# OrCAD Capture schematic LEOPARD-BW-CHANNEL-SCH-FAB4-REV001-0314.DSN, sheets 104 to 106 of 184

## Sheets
104 067_DDR4 DIMM CPU1 CHH-2: size A3; title: DDR4 DIMM CPU1 CHH-2
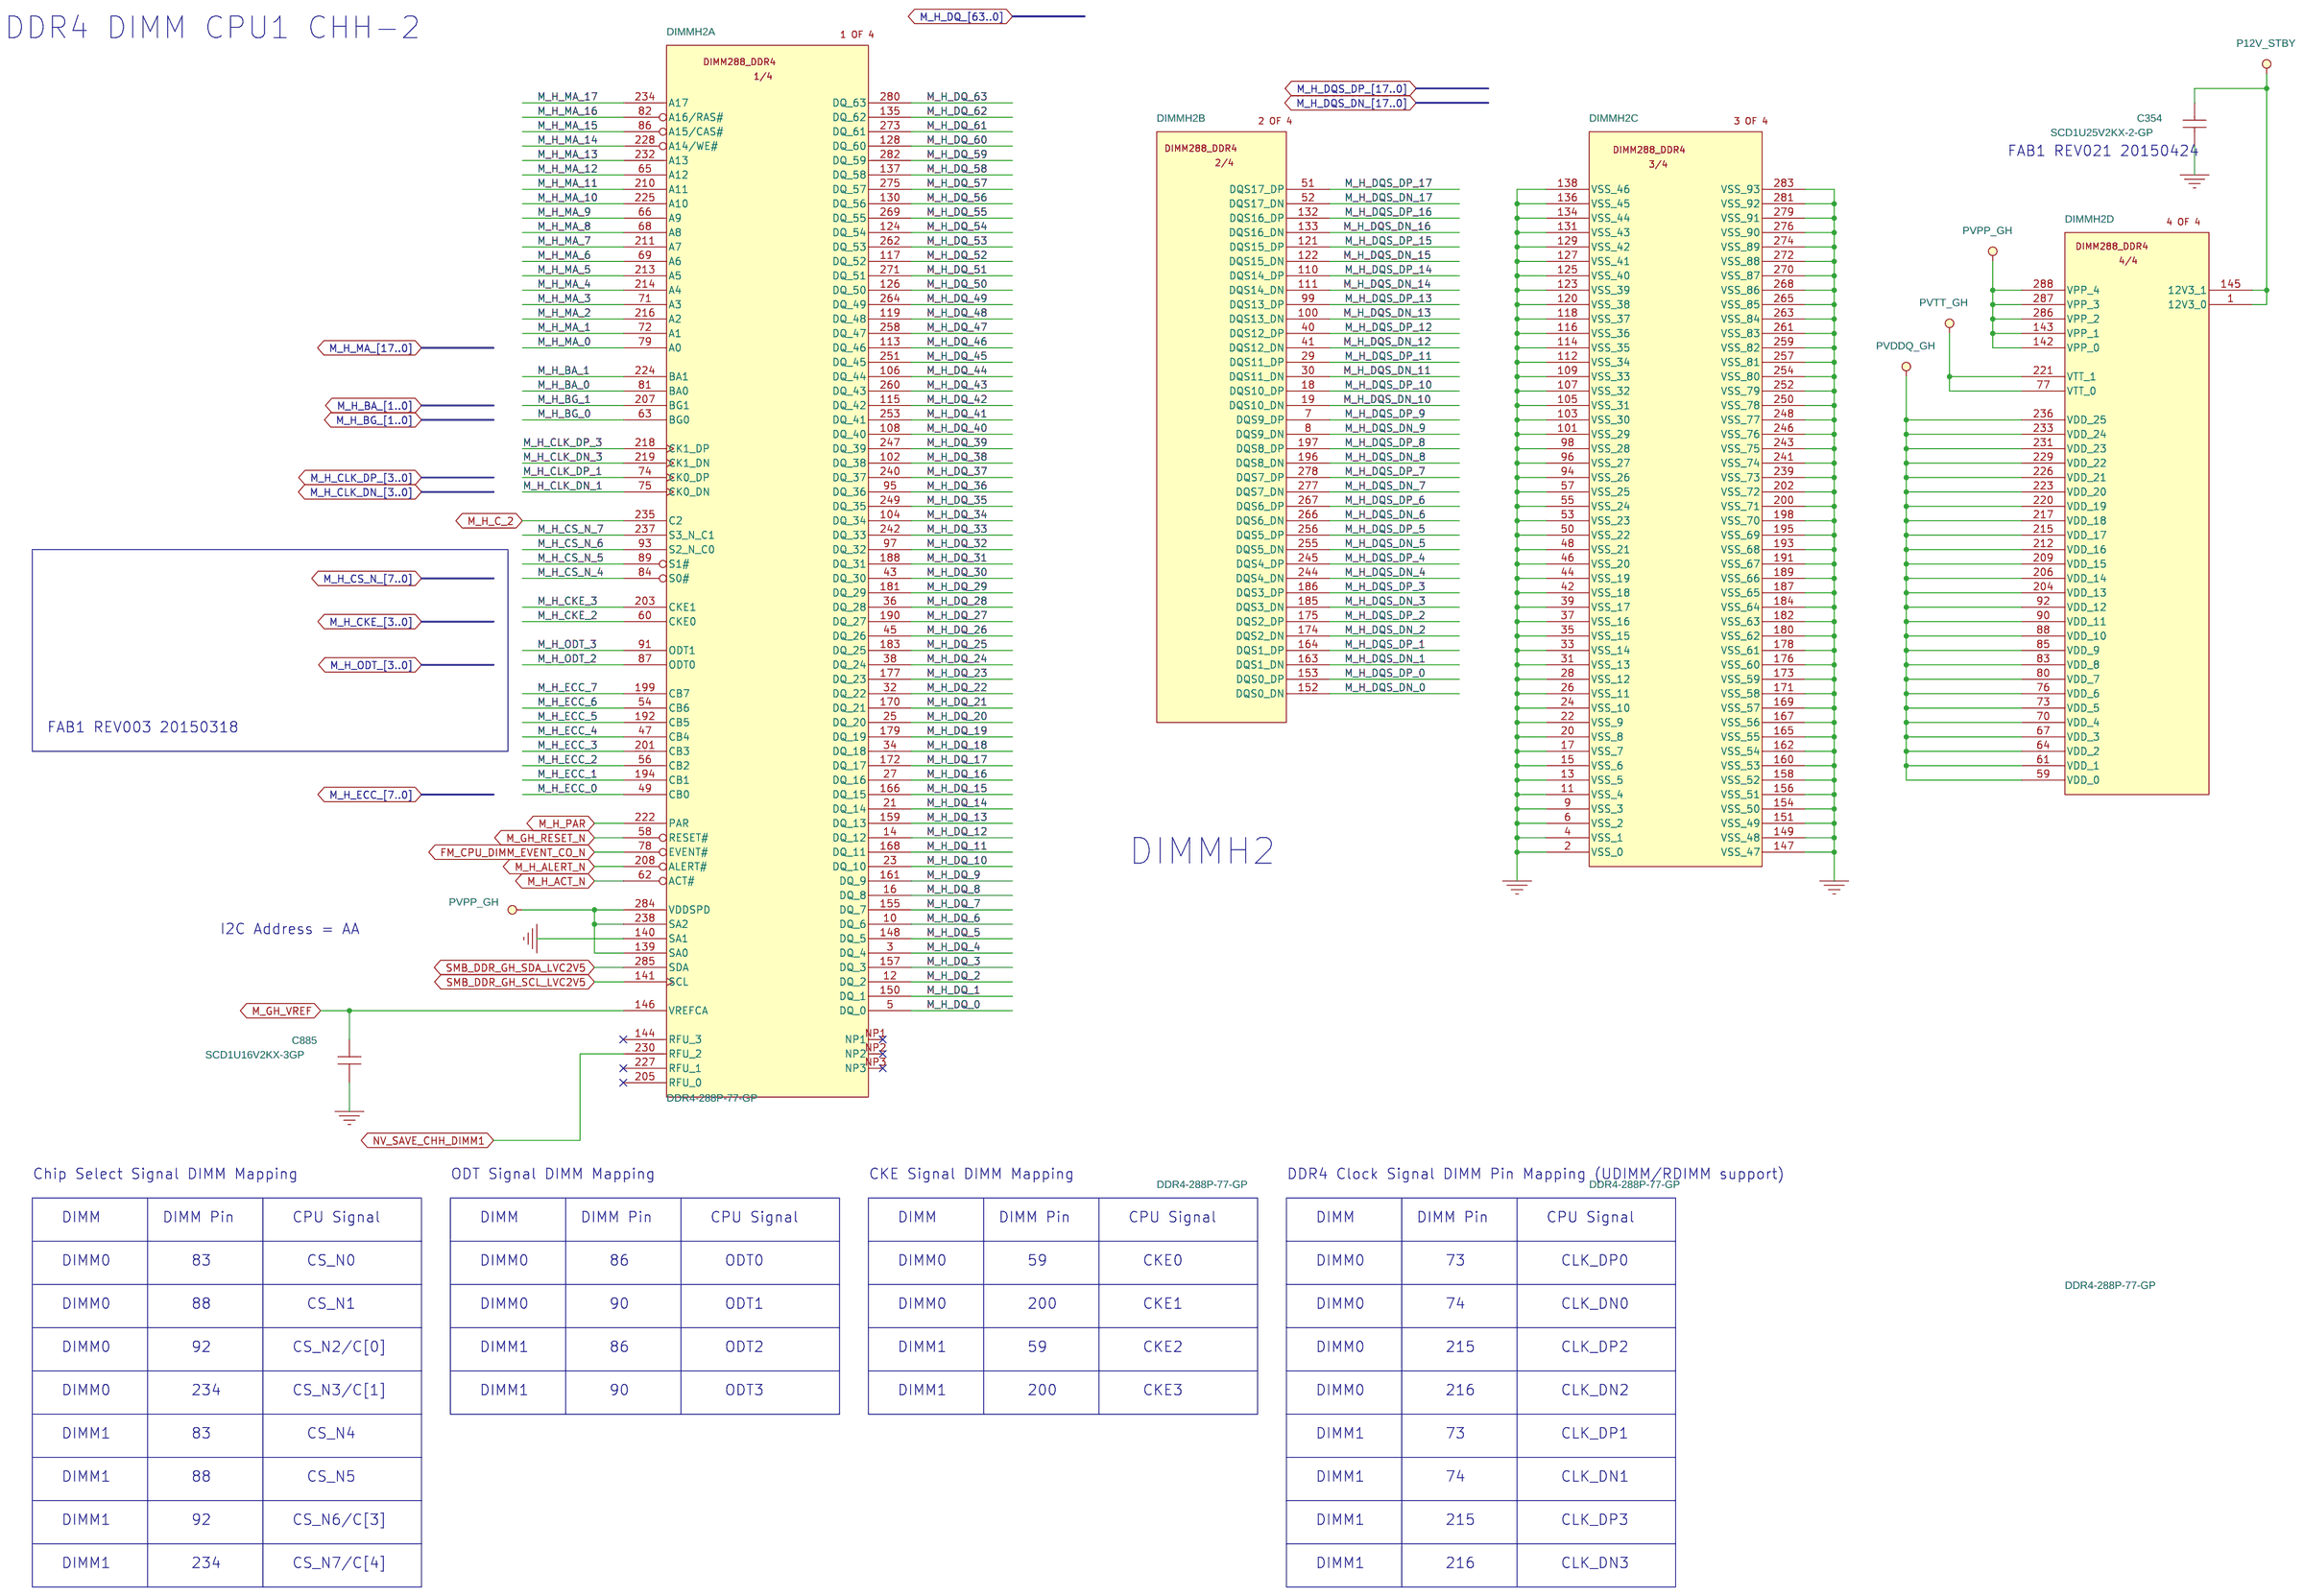
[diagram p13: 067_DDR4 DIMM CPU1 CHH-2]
105 066_DDR4 DIMM CPU1 CHH-1: size A3; title: DDR4 DIMM CPU1 CHH-1
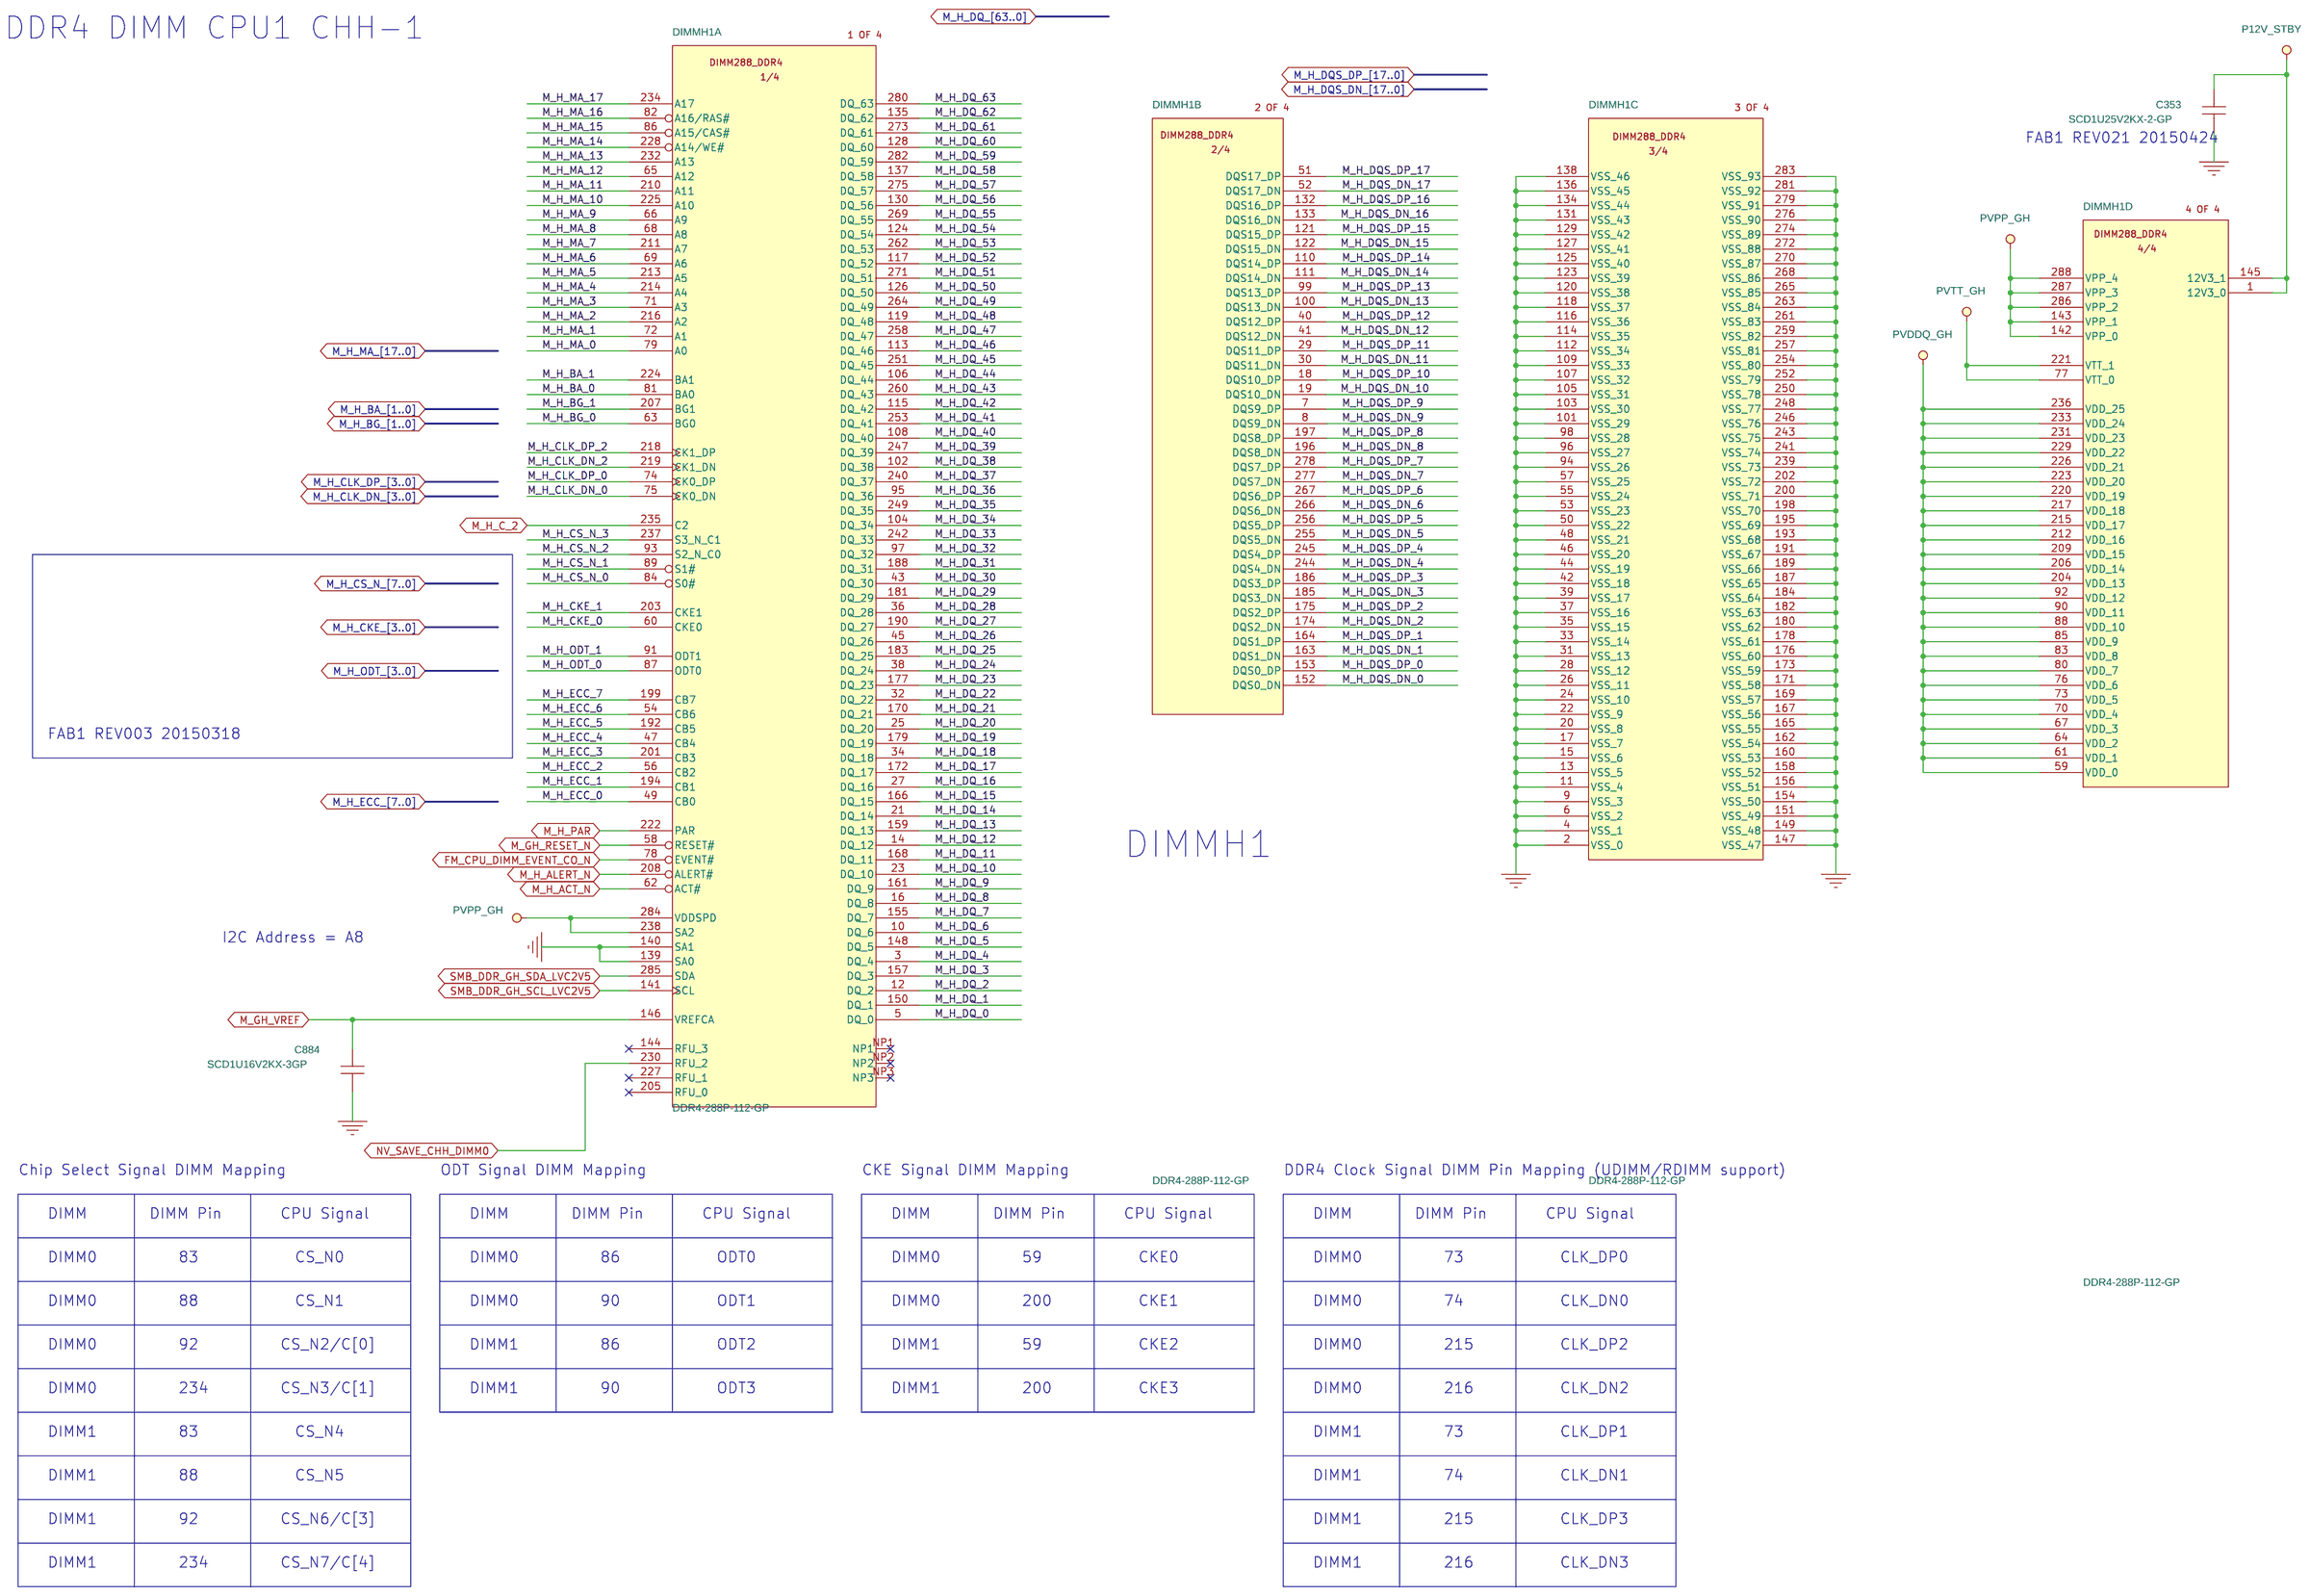
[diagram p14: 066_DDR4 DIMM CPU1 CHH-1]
106 065_DDR4 DIMM CPU1 CHG-2: size A3; title: DDR4 DIMM CPU1 CHG-2
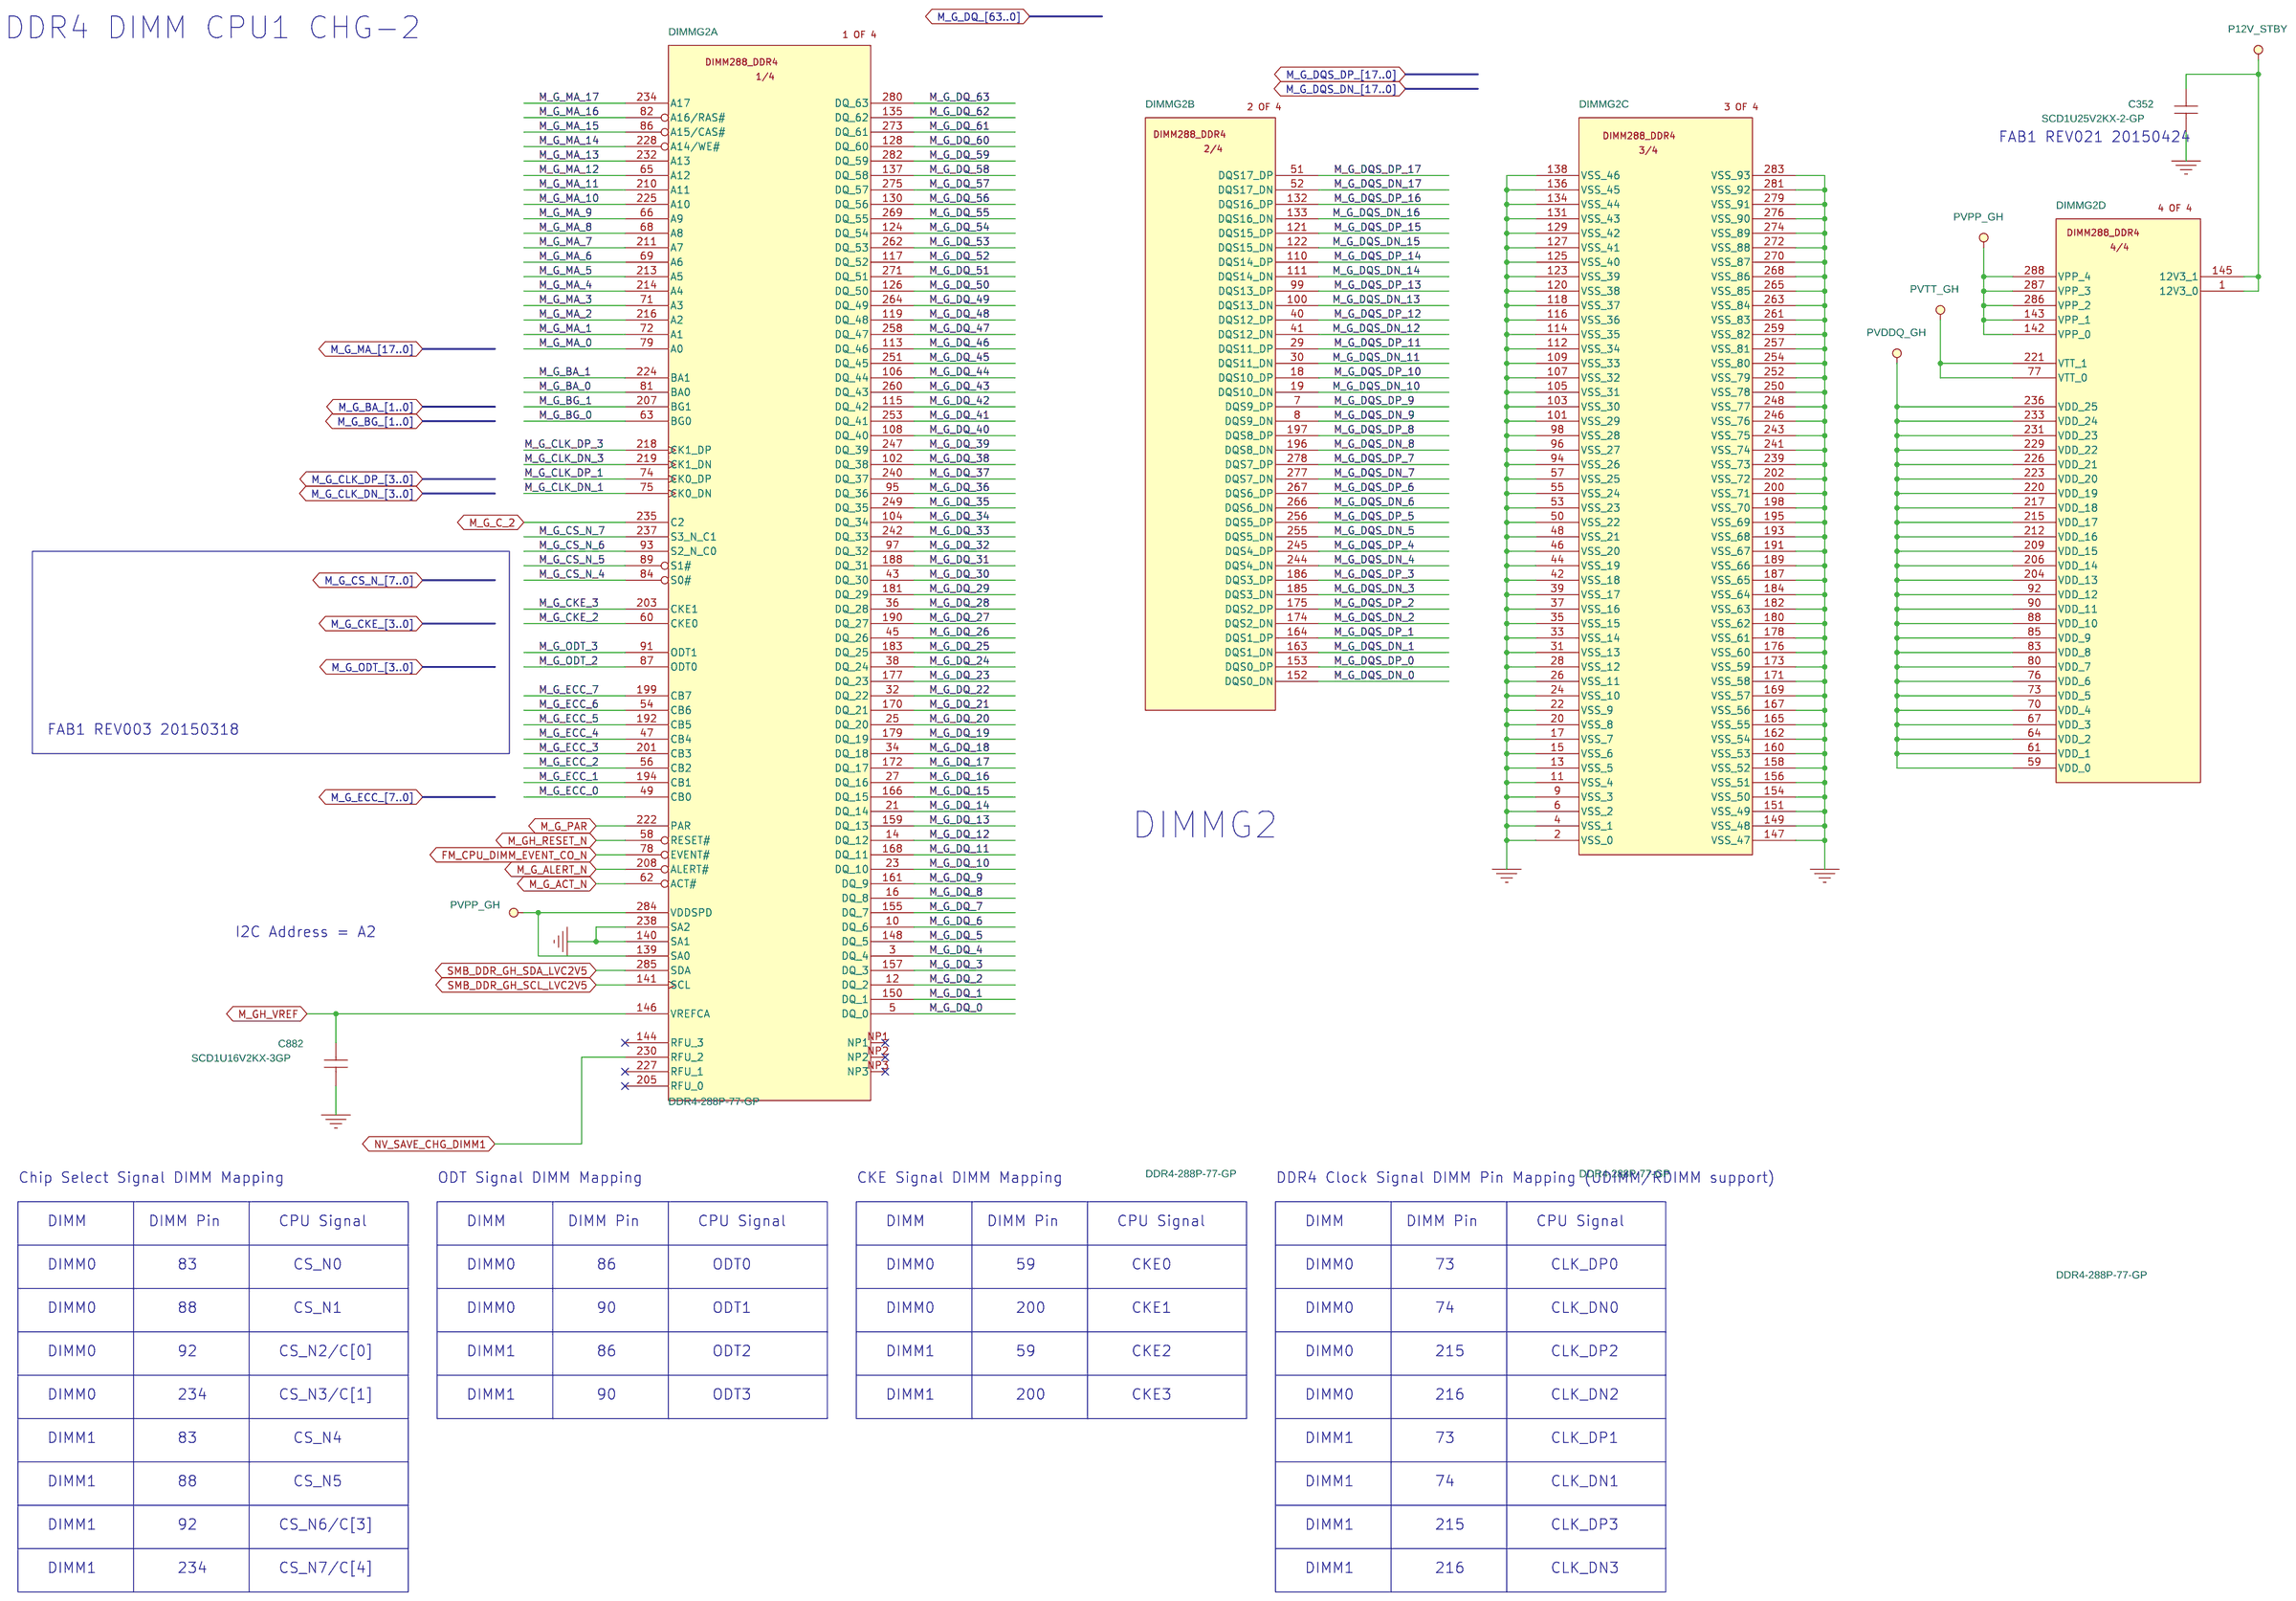
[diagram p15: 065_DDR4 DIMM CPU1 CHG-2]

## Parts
sheet 065_DDR4 DIMM CPU1 CHG-2
C352  SCD1U25V2KX-2-GP  [C402H22]
C882  SCD1U16V2KX-3GP  [C402H22]
DIMMG2  DDR4-288P-77-GP  [10124632-0001113LF]  (sections A,B,C,D)
sheet 066_DDR4 DIMM CPU1 CHH-1
C353  SCD1U25V2KX-2-GP  [C402H22]
C884  SCD1U16V2KX-3GP  [C402H22]
DIMMH1  DDR4-288P-112-GP  [10124632-0001113LF]  (sections A,B,C,D)
sheet 067_DDR4 DIMM CPU1 CHH-2
C354  SCD1U25V2KX-2-GP  [C402H22]
C885  SCD1U16V2KX-3GP  [C402H22]
DIMMH2  DDR4-288P-77-GP  [10124632-0001113LF]  (sections A,B,C,D)

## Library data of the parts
C352-C354 = SCD1U25V2KX-2-GP: CHIP CAP C 0.1U 25V K0402 X7R; GREENDFACTOR: R2_SA;HF_SA;G_SA;; Part Number: 78.10422.2FL; Part Type: SMD-BCG4; SPEC: http://wpqssvr.wistron.com.tw:7001/wpqs/servlet/COM.qpart.Attachment?PartNumber=78.10422.2FL
C882 C884 C885 = SCD1U16V2KX-3GP: CHIP CAP C 0.1U 16V K0402 X7R; CATEGORIES: CAP_1.xV; GREENDFACTOR: R2_SA;HF_SA;G_SA;; MAIN_SOURCE: M; Part Number: 78.10421.2FL; Part Type: SMD-BCG; SPEC: http://wpqssvr.wistron.com.tw:7001/wpqs/servlet/COM.qpart.Attachment?PartNumber=78.10421.2FL
DIMMG2 DIMMH2 = DDR4-288P-77-GP: SKT DIMM DDR4 288P 10124632-0001001LF; GREENDFACTOR: R2_SA;; POP?: 022.10010.0B11; Part Number: 22.10244.1A1; Part Type: SOCKET-G1; SPEC: http://wpqssvr.wistron.com.tw:7001/wpqs/servlet/COM.qpart.Attachment?PartNumber=22.10244.1A1
DIMMH1 = DDR4-288P-112-GP: SKT DIMM DDR4 288P 10124632-0003001LF; GREENDFACTOR: R2_C;; POP?: 022.10010.0E11; Part Number: 022.10010.0B91; Part Type: SOCKET-G2; SPEC: http://wpqssvr.wistron.com.tw:7001/wpqs/servlet/COM.qpart.Attachment?PartNumber=022.10010.0B91

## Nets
GND: C352.2 C353.2 C354.2 C882.2 C884.2 C885.2 DIMMG2.2(VSS_0) DIMMG2.4(VSS_1) DIMMG2.6(VSS_2) DIMMG2.9(VSS_3) DIMMG2.11(VSS_4) DIMMG2.13(VSS_5) DIMMG2.15(VSS_6) DIMMG2.17(VSS_7) DIMMG2.20(VSS_8) DIMMG2.22(VSS_9) DIMMG2.24(VSS_10) DIMMG2.26(VSS_11) DIMMG2.28(VSS_12) DIMMG2.31(VSS_13) DIMMG2.33(VSS_14) DIMMG2.35(VSS_15) DIMMG2.37(VSS_16) DIMMG2.39(VSS_17) DIMMG2.42(VSS_18) DIMMG2.44(VSS_19) DIMMG2.46(VSS_20) DIMMG2.48(VSS_21) DIMMG2.50(VSS_22) DIMMG2.53(VSS_23) DIMMG2.55(VSS_24) DIMMG2.57(VSS_25) DIMMG2.94(VSS_26) DIMMG2.96(VSS_27) DIMMG2.98(VSS_28) DIMMG2.101(VSS_29) DIMMG2.103(VSS_30) DIMMG2.105(VSS_31) DIMMG2.107(VSS_32) DIMMG2.109(VSS_33) DIMMG2.112(VSS_34) DIMMG2.114(VSS_35) DIMMG2.116(VSS_36) DIMMG2.118(VSS_37) DIMMG2.120(VSS_38) DIMMG2.123(VSS_39) DIMMG2.125(VSS_40) DIMMG2.127(VSS_41) DIMMG2.129(VSS_42) DIMMG2.131(VSS_43) DIMMG2.134(VSS_44) DIMMG2.136(VSS_45) DIMMG2.138(VSS_46) DIMMG2.140(SA1) DIMMG2.147(VSS_47) DIMMG2.149(VSS_48) DIMMG2.151(VSS_49) DIMMG2.154(VSS_50) DIMMG2.156(VSS_51) DIMMG2.158(VSS_52) DIMMG2.160(VSS_53) DIMMG2.162(VSS_54) DIMMG2.165(VSS_55) DIMMG2.167(VSS_56) DIMMG2.169(VSS_57) DIMMG2.171(VSS_58) DIMMG2.173(VSS_59) DIMMG2.176(VSS_60) DIMMG2.178(VSS_61) DIMMG2.180(VSS_62) DIMMG2.182(VSS_63) DIMMG2.184(VSS_64) DIMMG2.187(VSS_65) DIMMG2.189(VSS_66) DIMMG2.191(VSS_67) DIMMG2.193(VSS_68) DIMMG2.195(VSS_69) DIMMG2.198(VSS_70) DIMMG2.200(VSS_71) DIMMG2.202(VSS_72) DIMMG2.238(SA2) DIMMG2.239(VSS_73) DIMMG2.241(VSS_74) DIMMG2.243(VSS_75) DIMMG2.246(VSS_76) DIMMG2.248(VSS_77) DIMMG2.250(VSS_78) DIMMG2.252(VSS_79) DIMMG2.254(VSS_80) DIMMG2.257(VSS_81) DIMMG2.259(VSS_82) DIMMG2.261(VSS_83) DIMMG2.263(VSS_84) DIMMG2.265(VSS_85) DIMMG2.268(VSS_86) DIMMG2.270(VSS_87) DIMMG2.272(VSS_88) DIMMG2.274(VSS_89) DIMMG2.276(VSS_90) DIMMG2.279(VSS_91) DIMMG2.281(VSS_92) DIMMG2.283(VSS_93) DIMMH1.2(VSS_0) DIMMH1.4(VSS_1) DIMMH1.6(VSS_2) DIMMH1.9(VSS_3) DIMMH1.11(VSS_4) DIMMH1.13(VSS_5) DIMMH1.15(VSS_6) DIMMH1.17(VSS_7) DIMMH1.20(VSS_8) DIMMH1.22(VSS_9) DIMMH1.24(VSS_10) DIMMH1.26(VSS_11) DIMMH1.28(VSS_12) DIMMH1.31(VSS_13) DIMMH1.33(VSS_14) DIMMH1.35(VSS_15) DIMMH1.37(VSS_16) DIMMH1.39(VSS_17) DIMMH1.42(VSS_18) DIMMH1.44(VSS_19) DIMMH1.46(VSS_20) DIMMH1.48(VSS_21) DIMMH1.50(VSS_22) DIMMH1.53(VSS_23) DIMMH1.55(VSS_24) DIMMH1.57(VSS_25) DIMMH1.94(VSS_26) DIMMH1.96(VSS_27) DIMMH1.98(VSS_28) DIMMH1.101(VSS_29) DIMMH1.103(VSS_30) DIMMH1.105(VSS_31) DIMMH1.107(VSS_32) DIMMH1.109(VSS_33) DIMMH1.112(VSS_34) DIMMH1.114(VSS_35) DIMMH1.116(VSS_36) DIMMH1.118(VSS_37) DIMMH1.120(VSS_38) DIMMH1.123(VSS_39) DIMMH1.125(VSS_40) DIMMH1.127(VSS_41) DIMMH1.129(VSS_42) DIMMH1.131(VSS_43) DIMMH1.134(VSS_44) DIMMH1.136(VSS_45) DIMMH1.138(VSS_46) DIMMH1.139(SA0) DIMMH1.140(SA1) DIMMH1.147(VSS_47) DIMMH1.149(VSS_48) DIMMH1.151(VSS_49) DIMMH1.154(VSS_50) DIMMH1.156(VSS_51) DIMMH1.158(VSS_52) DIMMH1.160(VSS_53) DIMMH1.162(VSS_54) DIMMH1.165(VSS_55) DIMMH1.167(VSS_56) DIMMH1.169(VSS_57) DIMMH1.171(VSS_58) DIMMH1.173(VSS_59) DIMMH1.176(VSS_60) DIMMH1.178(VSS_61) DIMMH1.180(VSS_62) DIMMH1.182(VSS_63) DIMMH1.184(VSS_64) DIMMH1.187(VSS_65) DIMMH1.189(VSS_66) DIMMH1.191(VSS_67) DIMMH1.193(VSS_68) DIMMH1.195(VSS_69) DIMMH1.198(VSS_70) DIMMH1.200(VSS_71) DIMMH1.202(VSS_72) DIMMH1.239(VSS_73) DIMMH1.241(VSS_74) DIMMH1.243(VSS_75) DIMMH1.246(VSS_76) DIMMH1.248(VSS_77) DIMMH1.250(VSS_78) DIMMH1.252(VSS_79) DIMMH1.254(VSS_80) DIMMH1.257(VSS_81) DIMMH1.259(VSS_82) DIMMH1.261(VSS_83) DIMMH1.263(VSS_84) DIMMH1.265(VSS_85) DIMMH1.268(VSS_86) DIMMH1.270(VSS_87) DIMMH1.272(VSS_88) DIMMH1.274(VSS_89) DIMMH1.276(VSS_90) DIMMH1.279(VSS_91) DIMMH1.281(VSS_92) DIMMH1.283(VSS_93) DIMMH2.2(VSS_0) DIMMH2.4(VSS_1) DIMMH2.6(VSS_2) DIMMH2.9(VSS_3) DIMMH2.11(VSS_4) DIMMH2.13(VSS_5) DIMMH2.15(VSS_6) DIMMH2.17(VSS_7) DIMMH2.20(VSS_8) DIMMH2.22(VSS_9) DIMMH2.24(VSS_10) DIMMH2.26(VSS_11) DIMMH2.28(VSS_12) DIMMH2.31(VSS_13) DIMMH2.33(VSS_14) DIMMH2.35(VSS_15) DIMMH2.37(VSS_16) DIMMH2.39(VSS_17) DIMMH2.42(VSS_18) DIMMH2.44(VSS_19) DIMMH2.46(VSS_20) DIMMH2.48(VSS_21) DIMMH2.50(VSS_22) DIMMH2.53(VSS_23) DIMMH2.55(VSS_24) DIMMH2.57(VSS_25) DIMMH2.94(VSS_26) DIMMH2.96(VSS_27) DIMMH2.98(VSS_28) DIMMH2.101(VSS_29) DIMMH2.103(VSS_30) DIMMH2.105(VSS_31) DIMMH2.107(VSS_32) DIMMH2.109(VSS_33) DIMMH2.112(VSS_34) DIMMH2.114(VSS_35) DIMMH2.116(VSS_36) DIMMH2.118(VSS_37) DIMMH2.120(VSS_38) DIMMH2.123(VSS_39) DIMMH2.125(VSS_40) DIMMH2.127(VSS_41) DIMMH2.129(VSS_42) DIMMH2.131(VSS_43) DIMMH2.134(VSS_44) DIMMH2.136(VSS_45) DIMMH2.138(VSS_46) DIMMH2.140(SA1) DIMMH2.147(VSS_47) DIMMH2.149(VSS_48) DIMMH2.151(VSS_49) DIMMH2.154(VSS_50) DIMMH2.156(VSS_51) DIMMH2.158(VSS_52) DIMMH2.160(VSS_53) DIMMH2.162(VSS_54) DIMMH2.165(VSS_55) DIMMH2.167(VSS_56) DIMMH2.169(VSS_57) DIMMH2.171(VSS_58) DIMMH2.173(VSS_59) DIMMH2.176(VSS_60) DIMMH2.178(VSS_61) DIMMH2.180(VSS_62) DIMMH2.182(VSS_63) DIMMH2.184(VSS_64) DIMMH2.187(VSS_65) DIMMH2.189(VSS_66) DIMMH2.191(VSS_67) DIMMH2.193(VSS_68) DIMMH2.195(VSS_69) DIMMH2.198(VSS_70) DIMMH2.200(VSS_71) DIMMH2.202(VSS_72) DIMMH2.239(VSS_73) DIMMH2.241(VSS_74) DIMMH2.243(VSS_75) DIMMH2.246(VSS_76) DIMMH2.248(VSS_77) DIMMH2.250(VSS_78) DIMMH2.252(VSS_79) DIMMH2.254(VSS_80) DIMMH2.257(VSS_81) DIMMH2.259(VSS_82) DIMMH2.261(VSS_83) DIMMH2.263(VSS_84) DIMMH2.265(VSS_85) DIMMH2.268(VSS_86) DIMMH2.270(VSS_87) DIMMH2.272(VSS_88) DIMMH2.274(VSS_89) DIMMH2.276(VSS_90) DIMMH2.279(VSS_91) DIMMH2.281(VSS_92) DIMMH2.283(VSS_93) ; also on sheet 1 2 3 4 5 6 7 8 9 10 11 12 13 14 15 16 17 18 19 20 21 22 23 24 25 26 27 28 29 30 31 32 33 34 35 36 37 38 39 44 46 47 49 50 51 52 53 54 55 56 57 58 59 60 61 62 63 64 65 66 69 70 71 73 74 75 76 78 79 80 81 82 83 84 86 87 88 89 90 91 92 93 94 95 96 97 98 99 100 101 102 103 107 108 109 110 111 112 113 114 115 116 117 118 119 128 129 138 139 159 160 161 166 168 169 170 171 172 173 174 175 176 177 180 181 182 183 184
P12V_STBY: C352.1 C353.1 C354.1 DIMMG2.1(12V3_0) DIMMG2.145(12V3_1) DIMMH1.1(12V3_0) DIMMH1.145(12V3_1) DIMMH2.1(12V3_0) DIMMH2.145(12V3_1) ; also on sheet 2 3 4 7 9 10 11 12 13 17 18 22 23 27 28 32 36 59 60 75 95 107 108 109 110 111 112 113 114 115 116 117 118 119
PVDDQ_GH: DIMMG2.59(VDD_0) DIMMG2.61(VDD_1) DIMMG2.64(VDD_2) DIMMG2.67(VDD_3) DIMMG2.70(VDD_4) DIMMG2.73(VDD_5) DIMMG2.76(VDD_6) DIMMG2.80(VDD_7) DIMMG2.83(VDD_8) DIMMG2.85(VDD_9) DIMMG2.88(VDD_10) DIMMG2.90(VDD_11) DIMMG2.92(VDD_12) DIMMG2.204(VDD_13) DIMMG2.206(VDD_14) DIMMG2.209(VDD_15) DIMMG2.212(VDD_16) DIMMG2.215(VDD_17) DIMMG2.217(VDD_18) DIMMG2.220(VDD_19) DIMMG2.223(VDD_20) DIMMG2.226(VDD_21) DIMMG2.229(VDD_22) DIMMG2.231(VDD_23) DIMMG2.233(VDD_24) DIMMG2.236(VDD_25) DIMMH1.59(VDD_0) DIMMH1.61(VDD_1) DIMMH1.64(VDD_2) DIMMH1.67(VDD_3) DIMMH1.70(VDD_4) DIMMH1.73(VDD_5) DIMMH1.76(VDD_6) DIMMH1.80(VDD_7) DIMMH1.83(VDD_8) DIMMH1.85(VDD_9) DIMMH1.88(VDD_10) DIMMH1.90(VDD_11) DIMMH1.92(VDD_12) DIMMH1.204(VDD_13) DIMMH1.206(VDD_14) DIMMH1.209(VDD_15) DIMMH1.212(VDD_16) DIMMH1.215(VDD_17) DIMMH1.217(VDD_18) DIMMH1.220(VDD_19) DIMMH1.223(VDD_20) DIMMH1.226(VDD_21) DIMMH1.229(VDD_22) DIMMH1.231(VDD_23) DIMMH1.233(VDD_24) DIMMH1.236(VDD_25) DIMMH2.59(VDD_0) DIMMH2.61(VDD_1) DIMMH2.64(VDD_2) DIMMH2.67(VDD_3) DIMMH2.70(VDD_4) DIMMH2.73(VDD_5) DIMMH2.76(VDD_6) DIMMH2.80(VDD_7) DIMMH2.83(VDD_8) DIMMH2.85(VDD_9) DIMMH2.88(VDD_10) DIMMH2.90(VDD_11) DIMMH2.92(VDD_12) DIMMH2.204(VDD_13) DIMMH2.206(VDD_14) DIMMH2.209(VDD_15) DIMMH2.212(VDD_16) DIMMH2.215(VDD_17) DIMMH2.217(VDD_18) DIMMH2.220(VDD_19) DIMMH2.223(VDD_20) DIMMH2.226(VDD_21) DIMMH2.229(VDD_22) DIMMH2.231(VDD_23) DIMMH2.233(VDD_24) DIMMH2.236(VDD_25) ; also on sheet 13 15 45 97 107 120 129
FM_CPU_DIMM_EVENT_CO_N: DIMMG2.78(EVENT#) DIMMH1.78(EVENT#) DIMMH2.78(EVENT#) ; also on sheet 98 107 108 109 110 111 112 113 114 115 116 117 118 119
M_G_ACT_N: DIMMG2.62(ACT#) ; also on sheet 107 125
M_G_ALERT_N: DIMMG2.208(ALERT#) ; also on sheet 107 125
M_G_BA_0: DIMMG2.81(BA0) ; also on sheet 107 125
M_G_BA_1: DIMMG2.224(BA1) ; also on sheet 107 125
M_G_BG_0: DIMMG2.63(BG0) ; also on sheet 107 125
M_G_BG_1: DIMMG2.207(BG1) ; also on sheet 107 125
M_G_C_2: DIMMG2.235(C2) ; also on sheet 107 125
M_G_CKE_2: DIMMG2.60(CKE0) ; also on sheet 125
M_G_CKE_3: DIMMG2.203(CKE1) ; also on sheet 125
M_G_CLK_DN_1: DIMMG2.75(CK0_DN) ; also on sheet 125
M_G_CLK_DN_3: DIMMG2.219(CK1_DN) ; also on sheet 125
M_G_CLK_DP_1: DIMMG2.74(CK0_DP) ; also on sheet 125
M_G_CLK_DP_3: DIMMG2.218(CK1_DP) ; also on sheet 125
M_G_CS_N_4: DIMMG2.84(S0#) ; also on sheet 125
M_G_CS_N_5: DIMMG2.89(S1#) ; also on sheet 125
M_G_CS_N_6: DIMMG2.93(S2_N_C0) ; also on sheet 125
M_G_CS_N_7: DIMMG2.237(S3_N_C1) ; also on sheet 125
M_G_DQ_0: DIMMG2.5(DQ_0) ; also on sheet 107 125
M_G_DQ_1: DIMMG2.150(DQ_1) ; also on sheet 107 125
M_G_DQ_2: DIMMG2.12(DQ_2) ; also on sheet 107 125
M_G_DQ_3: DIMMG2.157(DQ_3) ; also on sheet 107 125
M_G_DQ_4: DIMMG2.3(DQ_4) ; also on sheet 107 125
M_G_DQ_5: DIMMG2.148(DQ_5) ; also on sheet 107 125
M_G_DQ_6: DIMMG2.10(DQ_6) ; also on sheet 107 125
M_G_DQ_7: DIMMG2.155(DQ_7) ; also on sheet 107 125
M_G_DQ_8: DIMMG2.16(DQ_8) ; also on sheet 107 125
M_G_DQ_9: DIMMG2.161(DQ_9) ; also on sheet 107 125
M_G_DQ_10: DIMMG2.23(DQ_10) ; also on sheet 107 125
M_G_DQ_11: DIMMG2.168(DQ_11) ; also on sheet 107 125
M_G_DQ_12: DIMMG2.14(DQ_12) ; also on sheet 107 125
M_G_DQ_13: DIMMG2.159(DQ_13) ; also on sheet 107 125
M_G_DQ_14: DIMMG2.21(DQ_14) ; also on sheet 107 125
M_G_DQ_15: DIMMG2.166(DQ_15) ; also on sheet 107 125
M_G_DQ_16: DIMMG2.27(DQ_16) ; also on sheet 107 125
M_G_DQ_17: DIMMG2.172(DQ_17) ; also on sheet 107 125
M_G_DQ_18: DIMMG2.34(DQ_18) ; also on sheet 107 125
M_G_DQ_19: DIMMG2.179(DQ_19) ; also on sheet 107 125
M_G_DQ_20: DIMMG2.25(DQ_20) ; also on sheet 107 125
M_G_DQ_21: DIMMG2.170(DQ_21) ; also on sheet 107 125
M_G_DQ_22: DIMMG2.32(DQ_22) ; also on sheet 107 125
M_G_DQ_23: DIMMG2.177(DQ_23) ; also on sheet 107 125
M_G_DQ_24: DIMMG2.38(DQ_24) ; also on sheet 107 125
M_G_DQ_25: DIMMG2.183(DQ_25) ; also on sheet 107 125
M_G_DQ_26: DIMMG2.45(DQ_26) ; also on sheet 107 125
M_G_DQ_27: DIMMG2.190(DQ_27) ; also on sheet 107 125
M_G_DQ_28: DIMMG2.36(DQ_28) ; also on sheet 107 125
M_G_DQ_29: DIMMG2.181(DQ_29) ; also on sheet 107 125
M_G_DQ_30: DIMMG2.43(DQ_30) ; also on sheet 107 125
M_G_DQ_31: DIMMG2.188(DQ_31) ; also on sheet 107 125
M_G_DQ_32: DIMMG2.97(DQ_32) ; also on sheet 107 125
M_G_DQ_33: DIMMG2.242(DQ_33) ; also on sheet 107 125
M_G_DQ_34: DIMMG2.104(DQ_34) ; also on sheet 107 125
M_G_DQ_35: DIMMG2.249(DQ_35) ; also on sheet 107 125
M_G_DQ_36: DIMMG2.95(DQ_36) ; also on sheet 107 125
M_G_DQ_37: DIMMG2.240(DQ_37) ; also on sheet 107 125
M_G_DQ_38: DIMMG2.102(DQ_38) ; also on sheet 107 125
M_G_DQ_39: DIMMG2.247(DQ_39) ; also on sheet 107 125
M_G_DQ_40: DIMMG2.108(DQ_40) ; also on sheet 107 125
M_G_DQ_41: DIMMG2.253(DQ_41) ; also on sheet 107 125
M_G_DQ_42: DIMMG2.115(DQ_42) ; also on sheet 107 125
M_G_DQ_43: DIMMG2.260(DQ_43) ; also on sheet 107 125
M_G_DQ_44: DIMMG2.106(DQ_44) ; also on sheet 107 125
M_G_DQ_45: DIMMG2.251(DQ_45) ; also on sheet 107 125
M_G_DQ_46: DIMMG2.113(DQ_46) ; also on sheet 107 125
M_G_DQ_47: DIMMG2.258(DQ_47) ; also on sheet 107 125
M_G_DQ_48: DIMMG2.119(DQ_48) ; also on sheet 107 125
M_G_DQ_49: DIMMG2.264(DQ_49) ; also on sheet 107 125
M_G_DQ_50: DIMMG2.126(DQ_50) ; also on sheet 107 125
M_G_DQ_51: DIMMG2.271(DQ_51) ; also on sheet 107 125
M_G_DQ_52: DIMMG2.117(DQ_52) ; also on sheet 107 125
M_G_DQ_53: DIMMG2.262(DQ_53) ; also on sheet 107 125
M_G_DQ_54: DIMMG2.124(DQ_54) ; also on sheet 107 125
M_G_DQ_55: DIMMG2.269(DQ_55) ; also on sheet 107 125
M_G_DQ_56: DIMMG2.130(DQ_56) ; also on sheet 107 125
M_G_DQ_57: DIMMG2.275(DQ_57) ; also on sheet 107 125
M_G_DQ_58: DIMMG2.137(DQ_58) ; also on sheet 107 125
M_G_DQ_59: DIMMG2.282(DQ_59) ; also on sheet 107 125
M_G_DQ_60: DIMMG2.128(DQ_60) ; also on sheet 107 125
M_G_DQ_61: DIMMG2.273(DQ_61) ; also on sheet 107 125
M_G_DQ_62: DIMMG2.135(DQ_62) ; also on sheet 107 125
M_G_DQ_63: DIMMG2.280(DQ_63) ; also on sheet 107 125
M_G_DQS_DN_0: DIMMG2.152(DQS0_DN) ; also on sheet 107 125
M_G_DQS_DN_1: DIMMG2.163(DQS1_DN) ; also on sheet 107 125
M_G_DQS_DN_2: DIMMG2.174(DQS2_DN) ; also on sheet 107 125
M_G_DQS_DN_3: DIMMG2.185(DQS3_DN) ; also on sheet 107 125
M_G_DQS_DN_4: DIMMG2.244(DQS4_DN) ; also on sheet 107 125
M_G_DQS_DN_5: DIMMG2.255(DQS5_DN) ; also on sheet 107 125
M_G_DQS_DN_6: DIMMG2.266(DQS6_DN) ; also on sheet 107 125
M_G_DQS_DN_7: DIMMG2.277(DQS7_DN) ; also on sheet 107 125
M_G_DQS_DN_8: DIMMG2.196(DQS8_DN) ; also on sheet 107 125
M_G_DQS_DN_9: DIMMG2.8(DQS9_DN) ; also on sheet 107 125
M_G_DQS_DN_10: DIMMG2.19(DQS10_DN) ; also on sheet 107 125
M_G_DQS_DN_11: DIMMG2.30(DQS11_DN) ; also on sheet 107 125
M_G_DQS_DN_12: DIMMG2.41(DQS12_DN) ; also on sheet 107 125
M_G_DQS_DN_13: DIMMG2.100(DQS13_DN) ; also on sheet 107 125
M_G_DQS_DN_14: DIMMG2.111(DQS14_DN) ; also on sheet 107 125
M_G_DQS_DN_15: DIMMG2.122(DQS15_DN) ; also on sheet 107 125
M_G_DQS_DN_16: DIMMG2.133(DQS16_DN) ; also on sheet 107 125
M_G_DQS_DN_17: DIMMG2.52(DQS17_DN) ; also on sheet 107 125
M_G_DQS_DP_0: DIMMG2.153(DQS0_DP) ; also on sheet 107 125
M_G_DQS_DP_1: DIMMG2.164(DQS1_DP) ; also on sheet 107 125
M_G_DQS_DP_2: DIMMG2.175(DQS2_DP) ; also on sheet 107 125
M_G_DQS_DP_3: DIMMG2.186(DQS3_DP) ; also on sheet 107 125
M_G_DQS_DP_4: DIMMG2.245(DQS4_DP) ; also on sheet 107 125
M_G_DQS_DP_5: DIMMG2.256(DQS5_DP) ; also on sheet 107 125
M_G_DQS_DP_6: DIMMG2.267(DQS6_DP) ; also on sheet 107 125
M_G_DQS_DP_7: DIMMG2.278(DQS7_DP) ; also on sheet 107 125
M_G_DQS_DP_8: DIMMG2.197(DQS8_DP) ; also on sheet 107 125
M_G_DQS_DP_9: DIMMG2.7(DQS9_DP) ; also on sheet 107 125
M_G_DQS_DP_10: DIMMG2.18(DQS10_DP) ; also on sheet 107 125
M_G_DQS_DP_11: DIMMG2.29(DQS11_DP) ; also on sheet 107 125
M_G_DQS_DP_12: DIMMG2.40(DQS12_DP) ; also on sheet 107 125
M_G_DQS_DP_13: DIMMG2.99(DQS13_DP) ; also on sheet 107 125
M_G_DQS_DP_14: DIMMG2.110(DQS14_DP) ; also on sheet 107 125
M_G_DQS_DP_15: DIMMG2.121(DQS15_DP) ; also on sheet 107 125
M_G_DQS_DP_16: DIMMG2.132(DQS16_DP) ; also on sheet 107 125
M_G_DQS_DP_17: DIMMG2.51(DQS17_DP) ; also on sheet 107 125
M_G_ECC_0: DIMMG2.49(CB0) ; also on sheet 107 125
M_G_ECC_1: DIMMG2.194(CB1) ; also on sheet 107 125
M_G_ECC_2: DIMMG2.56(CB2) ; also on sheet 107 125
M_G_ECC_3: DIMMG2.201(CB3) ; also on sheet 107 125
M_G_ECC_4: DIMMG2.47(CB4) ; also on sheet 107 125
M_G_ECC_5: DIMMG2.192(CB5) ; also on sheet 107 125
M_G_ECC_6: DIMMG2.54(CB6) ; also on sheet 107 125
M_G_ECC_7: DIMMG2.199(CB7) ; also on sheet 107 125
M_G_MA_0: DIMMG2.79(A0) ; also on sheet 107 125
M_G_MA_1: DIMMG2.72(A1) ; also on sheet 107 125
M_G_MA_2: DIMMG2.216(A2) ; also on sheet 107 125
M_G_MA_3: DIMMG2.71(A3) ; also on sheet 107 125
M_G_MA_4: DIMMG2.214(A4) ; also on sheet 107 125
M_G_MA_5: DIMMG2.213(A5) ; also on sheet 107 125
M_G_MA_6: DIMMG2.69(A6) ; also on sheet 107 125
M_G_MA_7: DIMMG2.211(A7) ; also on sheet 107 125
M_G_MA_8: DIMMG2.68(A8) ; also on sheet 107 125
M_G_MA_9: DIMMG2.66(A9) ; also on sheet 107 125
M_G_MA_10: DIMMG2.225(A10) ; also on sheet 107 125
M_G_MA_11: DIMMG2.210(A11) ; also on sheet 107 125
M_G_MA_12: DIMMG2.65(A12) ; also on sheet 107 125
M_G_MA_13: DIMMG2.232(A13) ; also on sheet 107 125
M_G_MA_14: DIMMG2.228(A14/WE#) ; also on sheet 107 125
M_G_MA_15: DIMMG2.86(A15/CAS#) ; also on sheet 107 125
M_G_MA_16: DIMMG2.82(A16/RAS#) ; also on sheet 107 125
M_G_MA_17: DIMMG2.234(A17) ; also on sheet 107 125
M_G_ODT_2: DIMMG2.87(ODT0) ; also on sheet 125
M_G_ODT_3: DIMMG2.91(ODT1) ; also on sheet 125
M_G_PAR: DIMMG2.222(PAR) ; also on sheet 107 125
M_GH_RESET_N: DIMMG2.58(RESET#) DIMMH1.58(RESET#) DIMMH2.58(RESET#) ; also on sheet 107 129
M_GH_VREF: C882.1 C884.1 C885.1 DIMMG2.146(VREFCA) DIMMH1.146(VREFCA) DIMMH2.146(VREFCA) ; also on sheet 107 129
M_H_ACT_N: DIMMH1.62(ACT#) DIMMH2.62(ACT#) ; also on sheet 124
M_H_ALERT_N: DIMMH1.208(ALERT#) DIMMH2.208(ALERT#) ; also on sheet 124
M_H_BA_0: DIMMH1.81(BA0) DIMMH2.81(BA0) ; also on sheet 124
M_H_BA_1: DIMMH1.224(BA1) DIMMH2.224(BA1) ; also on sheet 124
M_H_BG_0: DIMMH1.63(BG0) DIMMH2.63(BG0) ; also on sheet 124
M_H_BG_1: DIMMH1.207(BG1) DIMMH2.207(BG1) ; also on sheet 124
M_H_C_2: DIMMH1.235(C2) DIMMH2.235(C2) ; also on sheet 124
M_H_CKE_0: DIMMH1.60(CKE0) ; also on sheet 124
M_H_CKE_1: DIMMH1.203(CKE1) ; also on sheet 124
M_H_CKE_2: DIMMH2.60(CKE0) ; also on sheet 124
M_H_CKE_3: DIMMH2.203(CKE1) ; also on sheet 124
M_H_CLK_DN_0: DIMMH1.75(CK0_DN) ; also on sheet 124
M_H_CLK_DN_1: DIMMH2.75(CK0_DN) ; also on sheet 124
M_H_CLK_DN_2: DIMMH1.219(CK1_DN) ; also on sheet 124
M_H_CLK_DN_3: DIMMH2.219(CK1_DN) ; also on sheet 124
M_H_CLK_DP_0: DIMMH1.74(CK0_DP) ; also on sheet 124
M_H_CLK_DP_1: DIMMH2.74(CK0_DP) ; also on sheet 124
M_H_CLK_DP_2: DIMMH1.218(CK1_DP) ; also on sheet 124
M_H_CLK_DP_3: DIMMH2.218(CK1_DP) ; also on sheet 124
M_H_CS_N_0: DIMMH1.84(S0#) ; also on sheet 124
M_H_CS_N_1: DIMMH1.89(S1#) ; also on sheet 124
M_H_CS_N_2: DIMMH1.93(S2_N_C0) ; also on sheet 124
M_H_CS_N_3: DIMMH1.237(S3_N_C1) ; also on sheet 124
M_H_CS_N_4: DIMMH2.84(S0#) ; also on sheet 124
M_H_CS_N_5: DIMMH2.89(S1#) ; also on sheet 124
M_H_CS_N_6: DIMMH2.93(S2_N_C0) ; also on sheet 124
M_H_CS_N_7: DIMMH2.237(S3_N_C1) ; also on sheet 124
M_H_DQ_0: DIMMH1.5(DQ_0) DIMMH2.5(DQ_0) ; also on sheet 124
M_H_DQ_1: DIMMH1.150(DQ_1) DIMMH2.150(DQ_1) ; also on sheet 124
M_H_DQ_2: DIMMH1.12(DQ_2) DIMMH2.12(DQ_2) ; also on sheet 124
M_H_DQ_3: DIMMH1.157(DQ_3) DIMMH2.157(DQ_3) ; also on sheet 124
M_H_DQ_4: DIMMH1.3(DQ_4) DIMMH2.3(DQ_4) ; also on sheet 124
M_H_DQ_5: DIMMH1.148(DQ_5) DIMMH2.148(DQ_5) ; also on sheet 124
M_H_DQ_6: DIMMH1.10(DQ_6) DIMMH2.10(DQ_6) ; also on sheet 124
M_H_DQ_7: DIMMH1.155(DQ_7) DIMMH2.155(DQ_7) ; also on sheet 124
M_H_DQ_8: DIMMH1.16(DQ_8) DIMMH2.16(DQ_8) ; also on sheet 124
M_H_DQ_9: DIMMH1.161(DQ_9) DIMMH2.161(DQ_9) ; also on sheet 124
M_H_DQ_10: DIMMH1.23(DQ_10) DIMMH2.23(DQ_10) ; also on sheet 124
M_H_DQ_11: DIMMH1.168(DQ_11) DIMMH2.168(DQ_11) ; also on sheet 124
M_H_DQ_12: DIMMH1.14(DQ_12) DIMMH2.14(DQ_12) ; also on sheet 124
M_H_DQ_13: DIMMH1.159(DQ_13) DIMMH2.159(DQ_13) ; also on sheet 124
M_H_DQ_14: DIMMH1.21(DQ_14) DIMMH2.21(DQ_14) ; also on sheet 124
M_H_DQ_15: DIMMH1.166(DQ_15) DIMMH2.166(DQ_15) ; also on sheet 124
M_H_DQ_16: DIMMH1.27(DQ_16) DIMMH2.27(DQ_16) ; also on sheet 124
M_H_DQ_17: DIMMH1.172(DQ_17) DIMMH2.172(DQ_17) ; also on sheet 124
M_H_DQ_18: DIMMH1.34(DQ_18) DIMMH2.34(DQ_18) ; also on sheet 124
M_H_DQ_19: DIMMH1.179(DQ_19) DIMMH2.179(DQ_19) ; also on sheet 124
M_H_DQ_20: DIMMH1.25(DQ_20) DIMMH2.25(DQ_20) ; also on sheet 124
M_H_DQ_21: DIMMH1.170(DQ_21) DIMMH2.170(DQ_21) ; also on sheet 124
M_H_DQ_22: DIMMH1.32(DQ_22) DIMMH2.32(DQ_22) ; also on sheet 124
M_H_DQ_23: DIMMH1.177(DQ_23) DIMMH2.177(DQ_23) ; also on sheet 124
M_H_DQ_24: DIMMH1.38(DQ_24) DIMMH2.38(DQ_24) ; also on sheet 124
M_H_DQ_25: DIMMH1.183(DQ_25) DIMMH2.183(DQ_25) ; also on sheet 124
M_H_DQ_26: DIMMH1.45(DQ_26) DIMMH2.45(DQ_26) ; also on sheet 124
M_H_DQ_27: DIMMH1.190(DQ_27) DIMMH2.190(DQ_27) ; also on sheet 124
M_H_DQ_28: DIMMH1.36(DQ_28) DIMMH2.36(DQ_28) ; also on sheet 124
M_H_DQ_29: DIMMH1.181(DQ_29) DIMMH2.181(DQ_29) ; also on sheet 124
M_H_DQ_30: DIMMH1.43(DQ_30) DIMMH2.43(DQ_30) ; also on sheet 124
M_H_DQ_31: DIMMH1.188(DQ_31) DIMMH2.188(DQ_31) ; also on sheet 124
M_H_DQ_32: DIMMH1.97(DQ_32) DIMMH2.97(DQ_32) ; also on sheet 124
M_H_DQ_33: DIMMH1.242(DQ_33) DIMMH2.242(DQ_33) ; also on sheet 124
M_H_DQ_34: DIMMH1.104(DQ_34) DIMMH2.104(DQ_34) ; also on sheet 124
M_H_DQ_35: DIMMH1.249(DQ_35) DIMMH2.249(DQ_35) ; also on sheet 124
M_H_DQ_36: DIMMH1.95(DQ_36) DIMMH2.95(DQ_36) ; also on sheet 124
M_H_DQ_37: DIMMH1.240(DQ_37) DIMMH2.240(DQ_37) ; also on sheet 124
M_H_DQ_38: DIMMH1.102(DQ_38) DIMMH2.102(DQ_38) ; also on sheet 124
M_H_DQ_39: DIMMH1.247(DQ_39) DIMMH2.247(DQ_39) ; also on sheet 124
M_H_DQ_40: DIMMH1.108(DQ_40) DIMMH2.108(DQ_40) ; also on sheet 124
M_H_DQ_41: DIMMH1.253(DQ_41) DIMMH2.253(DQ_41) ; also on sheet 124
M_H_DQ_42: DIMMH1.115(DQ_42) DIMMH2.115(DQ_42) ; also on sheet 124
M_H_DQ_43: DIMMH1.260(DQ_43) DIMMH2.260(DQ_43) ; also on sheet 124
M_H_DQ_44: DIMMH1.106(DQ_44) DIMMH2.106(DQ_44) ; also on sheet 124
M_H_DQ_45: DIMMH1.251(DQ_45) DIMMH2.251(DQ_45) ; also on sheet 124
M_H_DQ_46: DIMMH1.113(DQ_46) DIMMH2.113(DQ_46) ; also on sheet 124
M_H_DQ_47: DIMMH1.258(DQ_47) DIMMH2.258(DQ_47) ; also on sheet 124
M_H_DQ_48: DIMMH1.119(DQ_48) DIMMH2.119(DQ_48) ; also on sheet 124
M_H_DQ_49: DIMMH1.264(DQ_49) DIMMH2.264(DQ_49) ; also on sheet 124
M_H_DQ_50: DIMMH1.126(DQ_50) DIMMH2.126(DQ_50) ; also on sheet 124
M_H_DQ_51: DIMMH1.271(DQ_51) DIMMH2.271(DQ_51) ; also on sheet 124
M_H_DQ_52: DIMMH1.117(DQ_52) DIMMH2.117(DQ_52) ; also on sheet 124
M_H_DQ_53: DIMMH1.262(DQ_53) DIMMH2.262(DQ_53) ; also on sheet 124
M_H_DQ_54: DIMMH1.124(DQ_54) DIMMH2.124(DQ_54) ; also on sheet 124
M_H_DQ_55: DIMMH1.269(DQ_55) DIMMH2.269(DQ_55) ; also on sheet 124
M_H_DQ_56: DIMMH1.130(DQ_56) DIMMH2.130(DQ_56) ; also on sheet 124
M_H_DQ_57: DIMMH1.275(DQ_57) DIMMH2.275(DQ_57) ; also on sheet 124
M_H_DQ_58: DIMMH1.137(DQ_58) DIMMH2.137(DQ_58) ; also on sheet 124
M_H_DQ_59: DIMMH1.282(DQ_59) DIMMH2.282(DQ_59) ; also on sheet 124
M_H_DQ_60: DIMMH1.128(DQ_60) DIMMH2.128(DQ_60) ; also on sheet 124
M_H_DQ_61: DIMMH1.273(DQ_61) DIMMH2.273(DQ_61) ; also on sheet 124
M_H_DQ_62: DIMMH1.135(DQ_62) DIMMH2.135(DQ_62) ; also on sheet 124
M_H_DQ_63: DIMMH1.280(DQ_63) DIMMH2.280(DQ_63) ; also on sheet 124
M_H_DQS_DN_0: DIMMH1.152(DQS0_DN) DIMMH2.152(DQS0_DN) ; also on sheet 124
M_H_DQS_DN_1: DIMMH1.163(DQS1_DN) DIMMH2.163(DQS1_DN) ; also on sheet 124
M_H_DQS_DN_2: DIMMH1.174(DQS2_DN) DIMMH2.174(DQS2_DN) ; also on sheet 124
M_H_DQS_DN_3: DIMMH1.185(DQS3_DN) DIMMH2.185(DQS3_DN) ; also on sheet 124
M_H_DQS_DN_4: DIMMH1.244(DQS4_DN) DIMMH2.244(DQS4_DN) ; also on sheet 124
M_H_DQS_DN_5: DIMMH1.255(DQS5_DN) DIMMH2.255(DQS5_DN) ; also on sheet 124
M_H_DQS_DN_6: DIMMH1.266(DQS6_DN) DIMMH2.266(DQS6_DN) ; also on sheet 124
M_H_DQS_DN_7: DIMMH1.277(DQS7_DN) DIMMH2.277(DQS7_DN) ; also on sheet 124
M_H_DQS_DN_8: DIMMH1.196(DQS8_DN) DIMMH2.196(DQS8_DN) ; also on sheet 124
M_H_DQS_DN_9: DIMMH1.8(DQS9_DN) DIMMH2.8(DQS9_DN) ; also on sheet 124
M_H_DQS_DN_10: DIMMH1.19(DQS10_DN) DIMMH2.19(DQS10_DN) ; also on sheet 124
M_H_DQS_DN_11: DIMMH1.30(DQS11_DN) DIMMH2.30(DQS11_DN) ; also on sheet 124
M_H_DQS_DN_12: DIMMH1.41(DQS12_DN) DIMMH2.41(DQS12_DN) ; also on sheet 124
M_H_DQS_DN_13: DIMMH1.100(DQS13_DN) DIMMH2.100(DQS13_DN) ; also on sheet 124
M_H_DQS_DN_14: DIMMH1.111(DQS14_DN) DIMMH2.111(DQS14_DN) ; also on sheet 124
M_H_DQS_DN_15: DIMMH1.122(DQS15_DN) DIMMH2.122(DQS15_DN) ; also on sheet 124
M_H_DQS_DN_16: DIMMH1.133(DQS16_DN) DIMMH2.133(DQS16_DN) ; also on sheet 124
M_H_DQS_DN_17: DIMMH1.52(DQS17_DN) DIMMH2.52(DQS17_DN) ; also on sheet 124
M_H_DQS_DP_0: DIMMH1.153(DQS0_DP) DIMMH2.153(DQS0_DP) ; also on sheet 124
M_H_DQS_DP_1: DIMMH1.164(DQS1_DP) DIMMH2.164(DQS1_DP) ; also on sheet 124
M_H_DQS_DP_2: DIMMH1.175(DQS2_DP) DIMMH2.175(DQS2_DP) ; also on sheet 124
M_H_DQS_DP_3: DIMMH1.186(DQS3_DP) DIMMH2.186(DQS3_DP) ; also on sheet 124
M_H_DQS_DP_4: DIMMH1.245(DQS4_DP) DIMMH2.245(DQS4_DP) ; also on sheet 124
M_H_DQS_DP_5: DIMMH1.256(DQS5_DP) DIMMH2.256(DQS5_DP) ; also on sheet 124
M_H_DQS_DP_6: DIMMH1.267(DQS6_DP) DIMMH2.267(DQS6_DP) ; also on sheet 124
M_H_DQS_DP_7: DIMMH1.278(DQS7_DP) DIMMH2.278(DQS7_DP) ; also on sheet 124
M_H_DQS_DP_8: DIMMH1.197(DQS8_DP) DIMMH2.197(DQS8_DP) ; also on sheet 124
M_H_DQS_DP_9: DIMMH1.7(DQS9_DP) DIMMH2.7(DQS9_DP) ; also on sheet 124
M_H_DQS_DP_10: DIMMH1.18(DQS10_DP) DIMMH2.18(DQS10_DP) ; also on sheet 124
M_H_DQS_DP_11: DIMMH1.29(DQS11_DP) DIMMH2.29(DQS11_DP) ; also on sheet 124
M_H_DQS_DP_12: DIMMH1.40(DQS12_DP) DIMMH2.40(DQS12_DP) ; also on sheet 124
M_H_DQS_DP_13: DIMMH1.99(DQS13_DP) DIMMH2.99(DQS13_DP) ; also on sheet 124
M_H_DQS_DP_14: DIMMH1.110(DQS14_DP) DIMMH2.110(DQS14_DP) ; also on sheet 124
M_H_DQS_DP_15: DIMMH1.121(DQS15_DP) DIMMH2.121(DQS15_DP) ; also on sheet 124
M_H_DQS_DP_16: DIMMH1.132(DQS16_DP) DIMMH2.132(DQS16_DP) ; also on sheet 124
M_H_DQS_DP_17: DIMMH1.51(DQS17_DP) DIMMH2.51(DQS17_DP) ; also on sheet 124
M_H_ECC_0: DIMMH1.49(CB0) DIMMH2.49(CB0) ; also on sheet 124
M_H_ECC_1: DIMMH1.194(CB1) DIMMH2.194(CB1) ; also on sheet 124
M_H_ECC_2: DIMMH1.56(CB2) DIMMH2.56(CB2) ; also on sheet 124
M_H_ECC_3: DIMMH1.201(CB3) DIMMH2.201(CB3) ; also on sheet 124
M_H_ECC_4: DIMMH1.47(CB4) DIMMH2.47(CB4) ; also on sheet 124
M_H_ECC_5: DIMMH1.192(CB5) DIMMH2.192(CB5) ; also on sheet 124
M_H_ECC_6: DIMMH1.54(CB6) DIMMH2.54(CB6) ; also on sheet 124
M_H_ECC_7: DIMMH1.199(CB7) DIMMH2.199(CB7) ; also on sheet 124
M_H_MA_0: DIMMH1.79(A0) DIMMH2.79(A0) ; also on sheet 124
M_H_MA_1: DIMMH1.72(A1) DIMMH2.72(A1) ; also on sheet 124
M_H_MA_2: DIMMH1.216(A2) DIMMH2.216(A2) ; also on sheet 124
M_H_MA_3: DIMMH1.71(A3) DIMMH2.71(A3) ; also on sheet 124
M_H_MA_4: DIMMH1.214(A4) DIMMH2.214(A4) ; also on sheet 124
M_H_MA_5: DIMMH1.213(A5) DIMMH2.213(A5) ; also on sheet 124
M_H_MA_6: DIMMH1.69(A6) DIMMH2.69(A6) ; also on sheet 124
M_H_MA_7: DIMMH1.211(A7) DIMMH2.211(A7) ; also on sheet 124
M_H_MA_8: DIMMH1.68(A8) DIMMH2.68(A8) ; also on sheet 124
M_H_MA_9: DIMMH1.66(A9) DIMMH2.66(A9) ; also on sheet 124
M_H_MA_10: DIMMH1.225(A10) DIMMH2.225(A10) ; also on sheet 124
M_H_MA_11: DIMMH1.210(A11) DIMMH2.210(A11) ; also on sheet 124
M_H_MA_12: DIMMH1.65(A12) DIMMH2.65(A12) ; also on sheet 124
M_H_MA_13: DIMMH1.232(A13) DIMMH2.232(A13) ; also on sheet 124
M_H_MA_14: DIMMH1.228(A14/WE#) DIMMH2.228(A14/WE#) ; also on sheet 124
M_H_MA_15: DIMMH1.86(A15/CAS#) DIMMH2.86(A15/CAS#) ; also on sheet 124
M_H_MA_16: DIMMH1.82(A16/RAS#) DIMMH2.82(A16/RAS#) ; also on sheet 124
M_H_MA_17: DIMMH1.234(A17) DIMMH2.234(A17) ; also on sheet 124
M_H_ODT_0: DIMMH1.87(ODT0) ; also on sheet 124
M_H_ODT_1: DIMMH1.91(ODT1) ; also on sheet 124
M_H_ODT_2: DIMMH2.87(ODT0) ; also on sheet 124
M_H_ODT_3: DIMMH2.91(ODT1) ; also on sheet 124
M_H_PAR: DIMMH1.222(PAR) DIMMH2.222(PAR) ; also on sheet 124
NV_SAVE_CHG_DIMM1: DIMMG2.230(RFU_2) ; also on sheet 52
NV_SAVE_CHH_DIMM0: DIMMH1.230(RFU_2) ; also on sheet 52
NV_SAVE_CHH_DIMM1: DIMMH2.230(RFU_2) ; also on sheet 52
PVPP_GH: DIMMG2.139(SA0) DIMMG2.142(VPP_0) DIMMG2.143(VPP_1) DIMMG2.284(VDDSPD) DIMMG2.286(VPP_2) DIMMG2.287(VPP_3) DIMMG2.288(VPP_4) DIMMH1.142(VPP_0) DIMMH1.143(VPP_1) DIMMH1.238(SA2) DIMMH1.284(VDDSPD) DIMMH1.286(VPP_2) DIMMH1.287(VPP_3) DIMMH1.288(VPP_4) DIMMH2.139(SA0) DIMMH2.142(VPP_0) DIMMH2.143(VPP_1) DIMMH2.238(SA2) DIMMH2.284(VDDSPD) DIMMH2.286(VPP_2) DIMMH2.287(VPP_3) DIMMH2.288(VPP_4) ; also on sheet 12 107 160
PVTT_GH: DIMMG2.77(VTT_0) DIMMG2.221(VTT_1) DIMMH1.77(VTT_0) DIMMH1.221(VTT_1) DIMMH2.77(VTT_0) DIMMH2.221(VTT_1) ; also on sheet 14 107
SMB_DDR_GH_SCL_LVC2V5: DIMMG2.141(SCL) DIMMH1.141(SCL) DIMMH2.141(SCL) ; also on sheet 107 160
SMB_DDR_GH_SDA_LVC2V5: DIMMG2.285(SDA) DIMMH1.285(SDA) DIMMH2.285(SDA) ; also on sheet 107 160

Not connected (* = marked no-connect by the designer): DIMMG2 144(RFU_3)* 205(RFU_0)* 227(RFU_1)* NP1* NP2* NP3*; DIMMH1 144(RFU_3)* 205(RFU_0)* 227(RFU_1)* NP1* NP2* NP3*; DIMMH2 144(RFU_3)* 205(RFU_0)* 227(RFU_1)* NP1* NP2* NP3*

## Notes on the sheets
sheet 104
- DDR4 DIMM CPU1 CHH-2
- FAB1 REV021 20150424
- FAB1 REV003 20150318
- DIMMH2
- I2C Address = AA
- Chip Select Signal DIMM Mapping
- ODT Signal DIMM Mapping
- CKE Signal DIMM Mapping
- DDR4 Clock Signal DIMM Pin Mapping (UDIMM/RDIMM support)
- DIMM
- DIMM Pin
- CPU Signal
- DIMM
- DIMM Pin
- CPU Signal
- DIMM
- DIMM Pin
- CPU Signal
- DIMM
- DIMM Pin
- CPU Signal
- DIMM0
- 83
- CS_N0
- DIMM0
- 86
- ODT0
- DIMM0
- 59
- CKE0
- DIMM0
- 73
- CLK_DP0
- DIMM0
- 88
- CS_N1
- DIMM0
- 90
- ODT1
- DIMM0
- 200
- CKE1
- DIMM0
- 74
- CLK_DN0
- DIMM0
- 92
- CS_N2/C[0]
- DIMM1
- 86
- ODT2
- DIMM1
- 59
- CKE2
- DIMM0
- 215
- CLK_DP2
- DIMM0
- 234
- CS_N3/C[1]
- DIMM1
- 90
- ODT3
- DIMM1
- 200
- CKE3
- DIMM0
- 216
- CLK_DN2
- DIMM1
- 83
- CS_N4
- DIMM1
- 73
- CLK_DP1
- DIMM1
- 88
- CS_N5
- DIMM1
- 74
- CLK_DN1
- DIMM1
- 92
- CS_N6/C[3]
- DIMM1
- 215
- CLK_DP3
- DIMM1
- 234
- CS_N7/C[4]
- DIMM1
- 216
- CLK_DN3
sheet 105
- DDR4 DIMM CPU1 CHH-1
- FAB1 REV021 20150424
- FAB1 REV003 20150318
- DIMMH1
- I2C Address = A8
- Chip Select Signal DIMM Mapping
- ODT Signal DIMM Mapping
- CKE Signal DIMM Mapping
- DDR4 Clock Signal DIMM Pin Mapping (UDIMM/RDIMM support)
- DIMM
- DIMM Pin
- CPU Signal
- DIMM
- DIMM Pin
- CPU Signal
- DIMM
- DIMM Pin
- CPU Signal
- DIMM
- DIMM Pin
- CPU Signal
- DIMM0
- 83
- CS_N0
- DIMM0
- 86
- ODT0
- DIMM0
- 59
- CKE0
- DIMM0
- 73
- CLK_DP0
- DIMM0
- 88
- CS_N1
- DIMM0
- 90
- ODT1
- DIMM0
- 200
- CKE1
- DIMM0
- 74
- CLK_DN0
- DIMM0
- 92
- CS_N2/C[0]
- DIMM1
- 86
- ODT2
- DIMM1
- 59
- CKE2
- DIMM0
- 215
- CLK_DP2
- DIMM0
- 234
- CS_N3/C[1]
- DIMM1
- 90
- ODT3
- DIMM1
- 200
- CKE3
- DIMM0
- 216
- CLK_DN2
- DIMM1
- 83
- CS_N4
- DIMM1
- 73
- CLK_DP1
- DIMM1
- 88
- CS_N5
- DIMM1
- 74
- CLK_DN1
- DIMM1
- 92
- CS_N6/C[3]
- DIMM1
- 215
- CLK_DP3
- DIMM1
- 234
- CS_N7/C[4]
- DIMM1
- 216
- CLK_DN3
sheet 106
- DDR4 DIMM CPU1 CHG-2
- FAB1 REV021 20150424
- FAB1 REV003 20150318
- DIMMG2
- I2C Address = A2
- Chip Select Signal DIMM Mapping
- ODT Signal DIMM Mapping
- CKE Signal DIMM Mapping
- DDR4 Clock Signal DIMM Pin Mapping (UDIMM/RDIMM support)
- DIMM
- DIMM Pin
- CPU Signal
- DIMM
- DIMM Pin
- CPU Signal
- DIMM
- DIMM Pin
- CPU Signal
- DIMM
- DIMM Pin
- CPU Signal
- DIMM0
- 83
- CS_N0
- DIMM0
- 86
- ODT0
- DIMM0
- 59
- CKE0
- DIMM0
- 73
- CLK_DP0
- DIMM0
- 88
- CS_N1
- DIMM0
- 90
- ODT1
- DIMM0
- 200
- CKE1
- DIMM0
- 74
- CLK_DN0
- DIMM0
- 92
- CS_N2/C[0]
- DIMM1
- 86
- ODT2
- DIMM1
- 59
- CKE2
- DIMM0
- 215
- CLK_DP2
- DIMM0
- 234
- CS_N3/C[1]
- DIMM1
- 90
- ODT3
- DIMM1
- 200
- CKE3
- DIMM0
- 216
- CLK_DN2
- DIMM1
- 83
- CS_N4
- DIMM1
- 73
- CLK_DP1
- DIMM1
- 88
- CS_N5
- DIMM1
- 74
- CLK_DN1
- DIMM1
- 92
- CS_N6/C[3]
- DIMM1
- 215
- CLK_DP3
- DIMM1
- 234
- CS_N7/C[4]
- DIMM1
- 216
- CLK_DN3
